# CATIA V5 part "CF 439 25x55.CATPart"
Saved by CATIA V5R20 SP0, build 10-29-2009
Part number: CF 439 25x55
Definition: NONE
Nomenclature: CF 439 25x55
Source: Unknown
Description: CF 439 25x55
Bounding box of the stored display mesh (mm): x -22 to 22, y 0 to 55, z -22 to 22
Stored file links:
  C:\Users\Utente\Desktop\IO LAVORO\3D X SITO CF\X SITO\CF 439\CF 439 25x55.CATPart
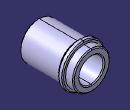
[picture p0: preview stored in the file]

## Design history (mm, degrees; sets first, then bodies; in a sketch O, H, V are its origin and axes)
Body1 "CF 439 25x55" (main body)
  Solid1: solid without history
